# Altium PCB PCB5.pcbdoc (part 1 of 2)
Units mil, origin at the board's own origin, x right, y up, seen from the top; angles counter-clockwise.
Board outline 1951.69 x 1930.99 mil, 2 copper layers (Top Layer, Bottom Layer); 57 components, 38 nets, 209 pads, 95 vias.
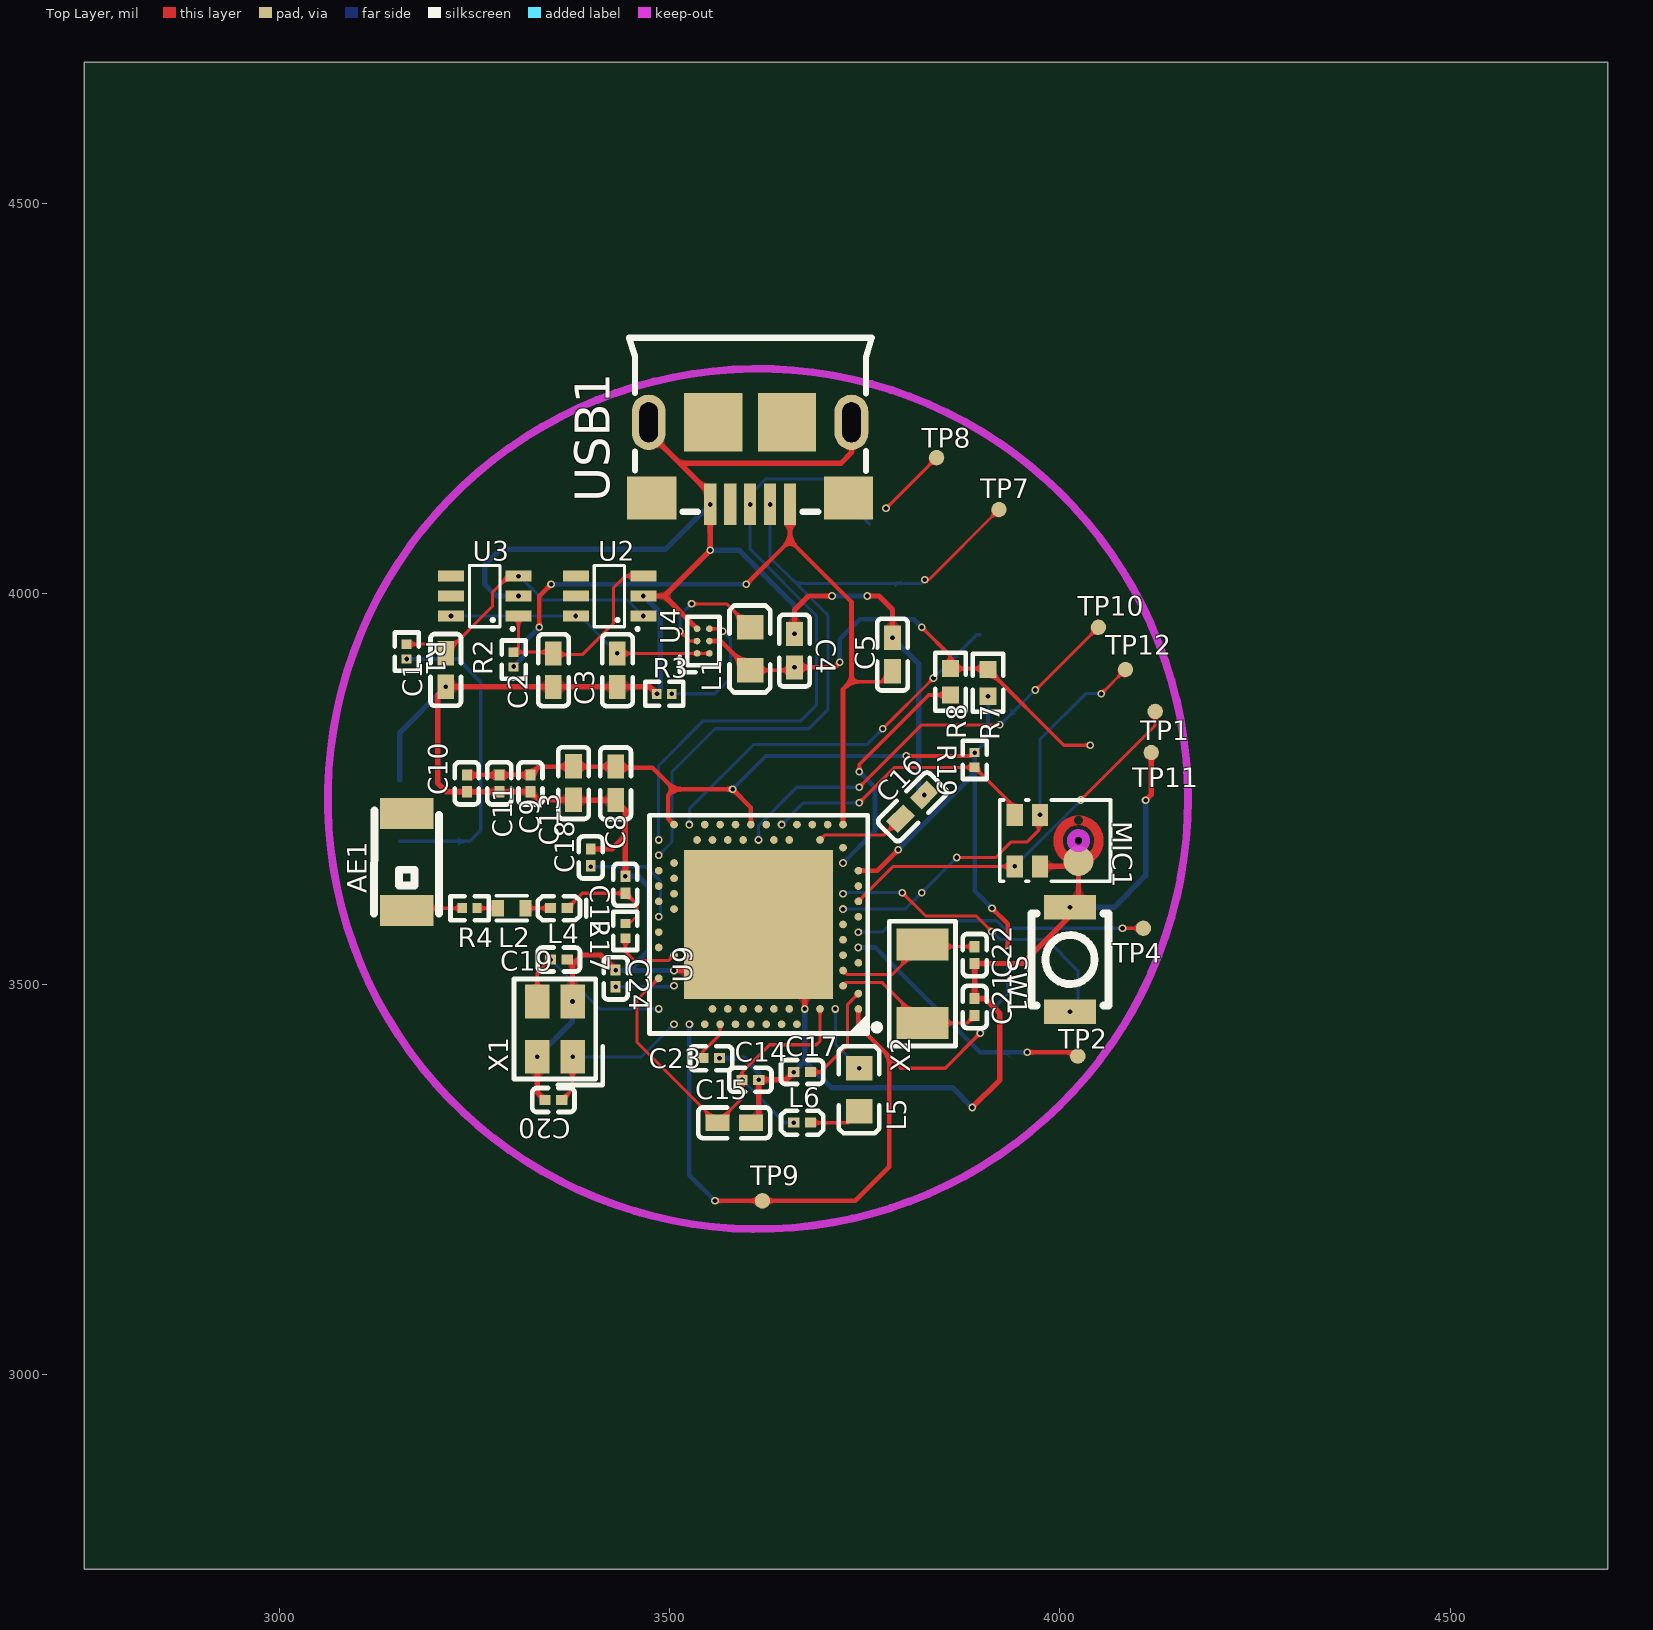
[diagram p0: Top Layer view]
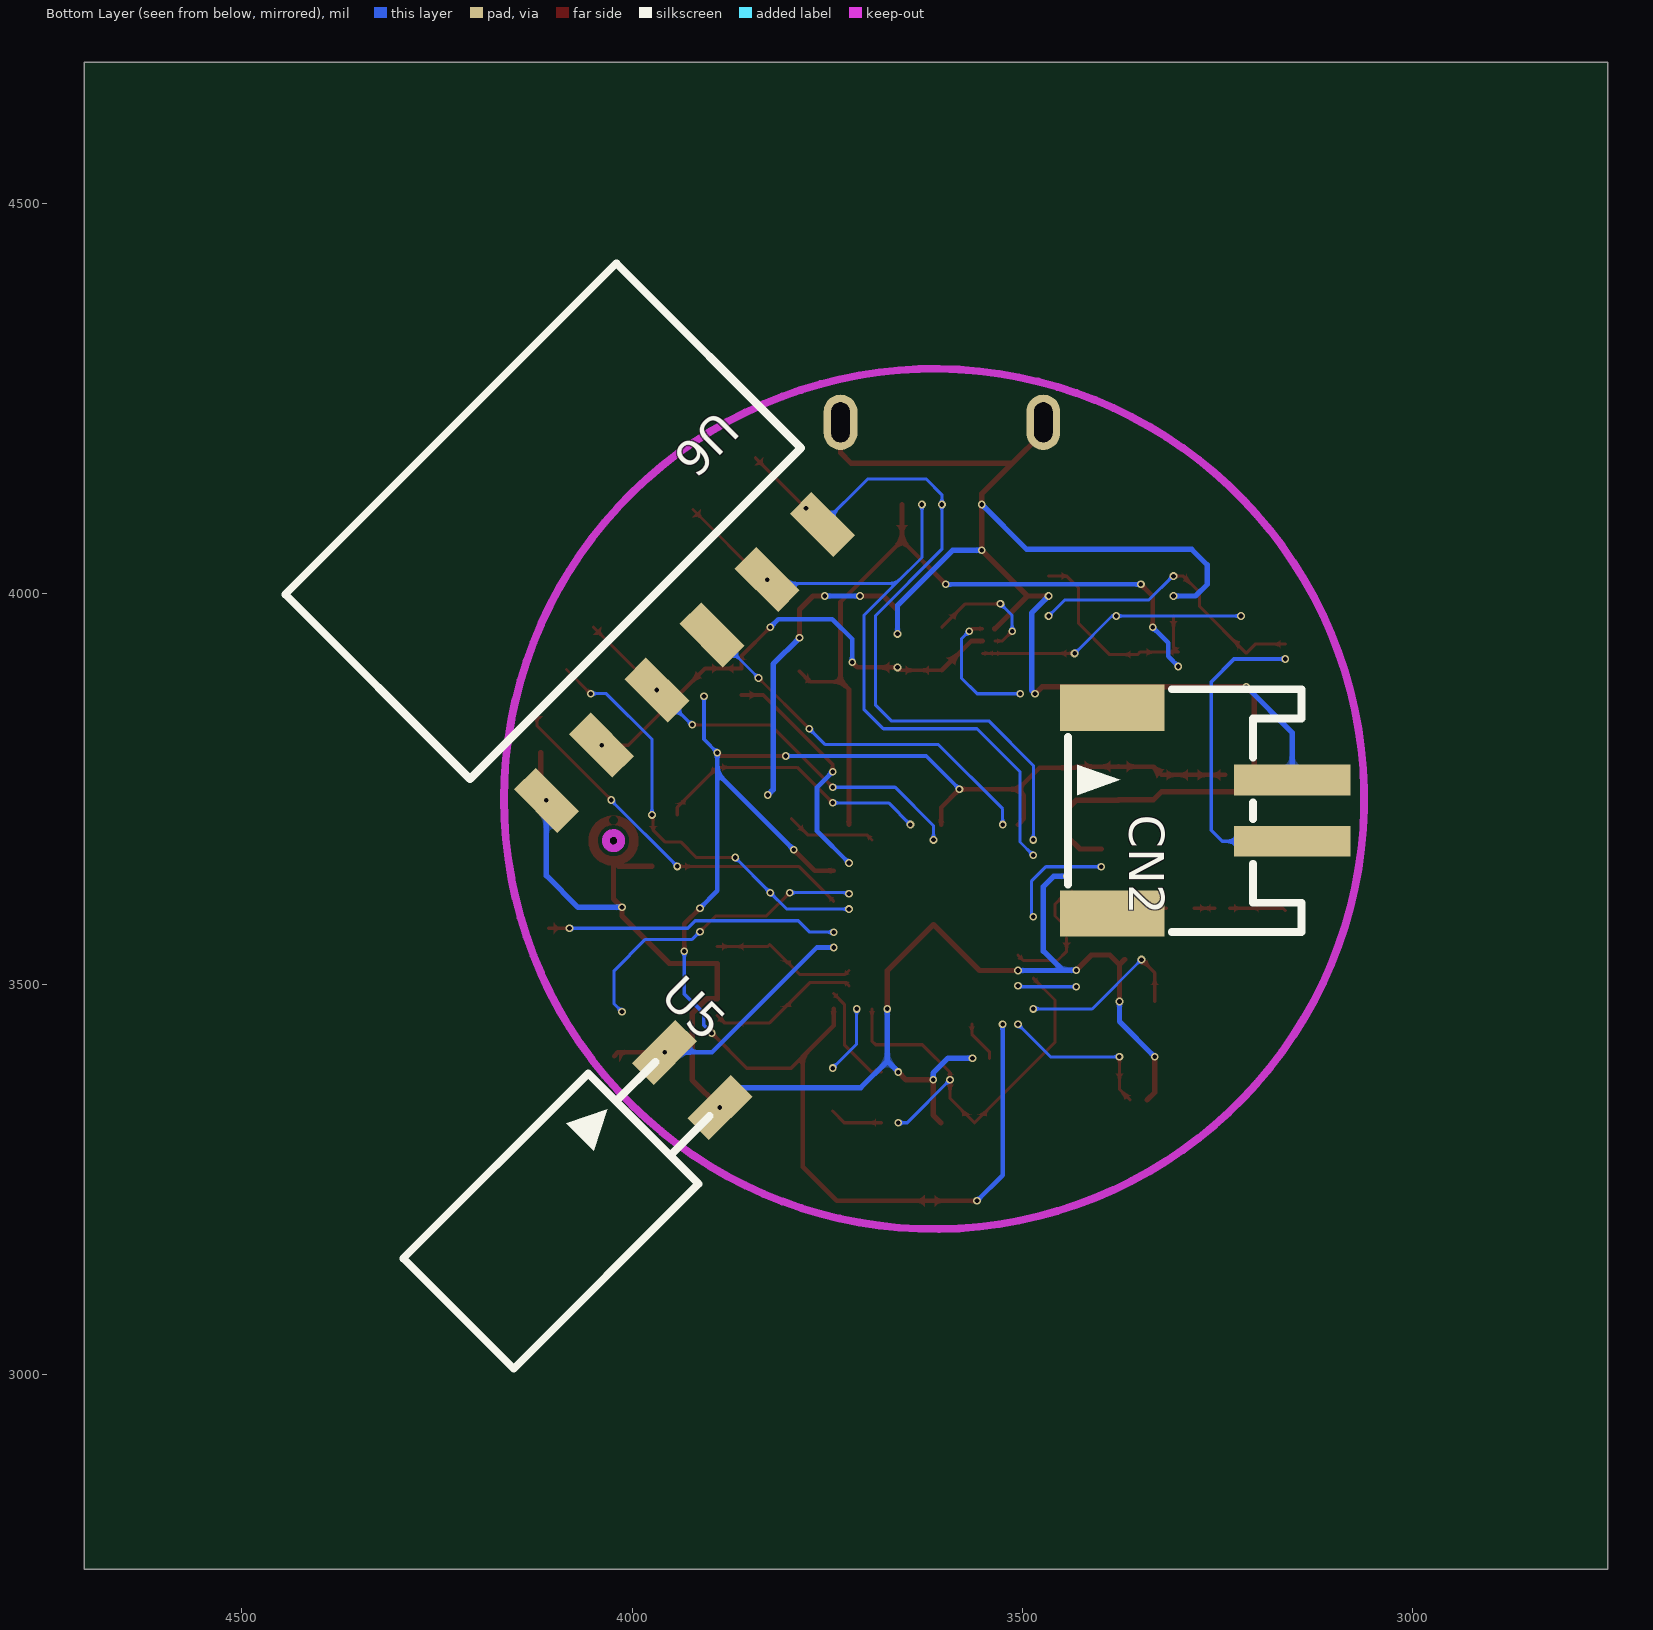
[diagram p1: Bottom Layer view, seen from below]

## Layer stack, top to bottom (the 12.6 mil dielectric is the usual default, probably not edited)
Top Layer: signal copper (thickness not stored)
Dielectric: dielectric 12.6, FR-4, Dk 4.8
Bottom Layer: signal copper (thickness not stored)

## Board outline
4701.69,2750 2750,2750 2750,4680.99 4701.69,4680.99

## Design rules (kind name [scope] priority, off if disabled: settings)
Clearance copperThickness1oz [All] p1: gap=7 ignorepadtopadclearanceinfootprint=FALSE except(4: Track-Track Track-Via Via-Via; 5: SMDPad-Via THPad-Via Via-Hole; 6: Track-SMDPad SMDPad-SMDPad Track-THPad SMDPad-THPad THPad-THPad Track-Fill SMDPad-Fill THPad-Fill Via-Fill Fill-Fill SMDPad-Region THPad-Region Via-Region Fill-Region Region-Region Track-Poly SMDPad-Poly THPad-Poly Via-Poly Fill-Poly Poly-Poly Track-Text SMDPad-Text THPad-Text Via-Text Fill-Text Region-Text Poly-Text Text-Text Track-Hole SMDPad-Hole THPad-Hole Fill-Hole Region-Hole Poly-Hole Text-Hole; 11.8: Track-Region Region-Poly Track-Sheet SMDPad-Sheet THPad-Sheet Via-Sheet Fill-Sheet Region-Sheet Poly-Sheet Text-Sheet Sheet-Hole)
Clearance copperThickness2oz [All] p1: gap=7 ignorepadtopadclearanceinfootprint=FALSE except(6: Track-SMDPad SMDPad-SMDPad Track-THPad SMDPad-THPad THPad-THPad Track-Via SMDPad-Via THPad-Via Via-Via Track-Fill SMDPad-Fill THPad-Fill Via-Fill Fill-Fill SMDPad-Region THPad-Region Via-Region Fill-Region Region-Region Track-Poly SMDPad-Poly THPad-Poly Via-Poly Fill-Poly Poly-Poly Track-Text SMDPad-Text THPad-Text Via-Text Fill-Text Region-Text Poly-Text Text-Text Track-Hole SMDPad-Hole THPad-Hole Via-Hole Fill-Hole Region-Hole Poly-Hole Text-Hole; 8: Track-Track; 11.8: Track-Region Region-Poly Track-Sheet SMDPad-Sheet THPad-Sheet Via-Sheet Fill-Sheet Region-Sheet Poly-Sheet Text-Sheet Sheet-Hole)
DiffPairsRouting differentialPair [All] p1: maxuncoupledlength=10 maxlimit=6 mostfreqgap=6 toplayer_minwidth=5 toplayer_prefwidth=10 toplayer_maxwidth=100 bottomlayer_minwidth=5 bottomlayer_prefwidth=10 bottomlayer_maxwidth=100
PasteMaskExpansion pasteMaskExpansion [All] p1:
PlaneConnect innerPlane [All] p1: planeconnectstyle=Relief reliefexpansion=20 reliefentries=4 reliefconductorwidth=10 reliefairgap=10
PolygonConnect copperRegion [All] p1: connectstyle=Relief reliefentries=4 reliefconductorwidth=10 polygonreliefangle="90 Angle" airgapwidth=10
RoutingVias viaSize [All] p1: viastyle="Through Hole" holewidth=5.9 minholewidth=5.9 maxholewidth=5.9 width=9.8 minwidth=9.8 maxwidth=9.8
SolderMaskExpansion solderMaskExpansion [All] p1: useseparateexpansions=TRUE expansion=2 expansionbottom=2
Width copperLine [All] p1: maxlimit=4 minlimit=4 preferedwidth=4
Width Source [All] p1: maxlimit=6 minlimit=5 preferedwidth=5
Width Ground [All] p1: maxlimit=7 minlimit=7 preferedwidth=7

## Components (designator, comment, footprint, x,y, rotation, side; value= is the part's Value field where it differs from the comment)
AE1 "2450AT18A100E" ANT-SMD_L3.2-W1.6 3162.94,3656.5 r90 top
C1 "CL05A105KQ5NNNC" C0402 3212.94,3902.61 r90 top
C2 "CL05A105KQ5NNNC" C0402 3350.93,3902.24 r90 top
C3 "CL05A106MP5NUNC" C0402 3432.94,3902.24 r90 top
C4 "GRM155R60J226ME11D" C0402 3659.84,3927.24 r270 top
C5 "C1005X6S0G475M050BC" C0402 3785.42,3922.24 r90 top
C8 "CL05A105KQ5NNNC" C0402 3430.67,3757.24 r90 top
C9 "GRM033C71C104KE14D" C0201 3321.52,3757.24 r270 top
C10 "GRM033C71C104KE14D" C0201 3239.95,3757.24 r270 top
C11 "GRM033C71C104KE14D" C0201 3281.61,3757.24 r270 top
C12 "0201CG0R5B250NT" C0201 3443.14,3627.24 r270 top
C13 "CL05A475KP5NRNC" C0402 3376.68,3757.65 r90 top
C14 "CL03A473KQ3NNNC" C0201 3603.34,3377.24 r0 top
C15 "GRM155R70J105KA12D" C0402 3582.58,3322.24 r180 top
C16 "CL05A475KP5NRNC" C0402 3810.9,3727.1 r225 top
C17 "CL03A104KQ3NNNC" C0201 3669.53,3387.24 r180 top
C18 "GRM0335C1E821JA01D" C0201 3398.74,3662.24 r270 top
C19 "GRM0335C1E120GA01D" C0201 3358.01,3531.44 r180 top
C20 "GRM0335C1E120GA01D" C0201 3350.91,3351.44 r0 top
C21 "GRM0335C1E120GA01D" C0201 3890.77,3470.64 r270 top
C22 "GRM0335C1E120GA01D" C0201 3890.77,3537.24 r90 top
C23 "GRM0335C1E821JA01D" C0201 3552.94,3405.02 r180 top
C24 "GRM0335C1E821JA01D" C0201 3430.67,3507.24 r270 top
CN2 "S2B-PH-SM4-TB(LF)(SN)" CONN-SMD_P2.00_S2B-PH-SM4-TB-LF-SN 3269.28,3722.24 r270 bottom
L1 "SLM16082R2MIT" L0603 3602.94,3929.69 r90 top
L2 "LQW15AN3N9C00D" IND-SMD_L1.0-W0.5-2 3297.4,3597.24 r180 top
L4 "LQP03TG2N7B02D" L0201-RD 3358.01,3597.24 r180 top
L5 "MLZ1608N100LT000" L0603 3742.99,3364.86 r90 top
L6 "LQP03TN15NJ02D" L0201 3669.53,3322.4 r0 top
MIC1 "MSM261D3526Z1CM" OCLGA-6_L3.5-W2.7-TL-MSM261D3526Z1CM 3982.94,3683.78 r90 top
R1 "RC0201JR-070RL" R0201 3162.94,3926.06 r90 top
R2 "RC0201JR-070RL" R0201 3299.92,3915.82 r90 top
R3 "RC0201FR-0756K2L" R0201 3492.94,3871.97 r0 top
R4 "RC0201JR-070RL" R0201 3243.55,3597.24 r180 top
R7 "RC0402FR-070RL" R0402 3907.78,3886.06 r270 top
R8 "RC0402FR-070RL" R0402 3859.77,3887.43 r270 top
R17 "RC0201JR-070RL" R0201 3443.14,3568.22 r270 top
R19 "RC0201JR-070RL" R0201 3890.77,3787.24 r90 top
SW1 "B3U-1000P" KEY-SMD_B3U-1000PM 4012.94,3531.44 r90 top
TP1 "Test-Point" Test-Point-0.5mm 4121.98,3849.41 r0 top
TP2 "Test-Point" Test-Point-0.5mm 4022.94,3407.75 r0 top
TP4 "Test-Point" Test-Point-0.5mm 4106.98,3571.52 r0 top
TP7 "Test-Point" Test-Point-0.5mm 3921.98,4108.16 r0 top
TP8 "Test-Point" Test-Point-0.5mm 3841.98,4174.64 r0 top
TP9 "Test-Point" Test-Point-0.5mm 3618.7,3222.24 r0 top
TP10 "Test-Point" Test-Point-0.5mm 4049.35,3957.24 r0 top
TP11 "Test-Point" Test-Point-0.5mm 4116.98,3796.75 r0 top
TP12 "Test-Point" Test-Point-0.5mm 4084.03,3903.1 r0 top
U2 "LM66100DCKT_C2832141" SC-70-6_L2.0-W1.3-P0.65-LS2.1-BL 3422.94,3997.24 r90 top
U3 "LM66100DCKT_C2832141" SC-70-6_L2.0-W1.3-P0.65-LS2.1-BL 3262.94,3997.24 r90 top
U4 "MAX38640AENT+" WLP-6_L1.4-W0.9-R2-C3-P0.40-TL 3542.94,3939.58 r90 top
U5 "X6511FRS-02-C85D30" HDR-SMD_2P-P2.54-H-F-L11.5 3922.94,3377.24 r225 bottom
U6 "X6511FRS-06-C85D30" HDR-SMD_6P-P2.54-H-F-L11.5 3932.94,3912.24 r315 bottom
U9 "NRF52840-QIAA-R" AQFN-73_L7.0-W7.0-P0.50-BL-EP4.8 3613.77,3576.44 r90 top
USB1 "10118193-0001LF" MICRO-USB-SMD_10118193-0001LF 3602.94,4167.24 r180 top
X1 "Q22FA1280002500" CRYSTAL-SMD_4P-L2.0-W1.6-BL 3352.82,3442.24 r90 top
X2 "NX3215SA-32.768K-STD-MUA-9" CRYSTAL-SMD_L3.2-W1.5-1 3823.74,3500.46 r90 top

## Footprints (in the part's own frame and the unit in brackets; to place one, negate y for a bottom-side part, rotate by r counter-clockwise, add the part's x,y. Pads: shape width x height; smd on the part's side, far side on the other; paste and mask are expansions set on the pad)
ANT-SMD_L3.2-W1.6 [mm]
  rect 1x1.75 smd: 1(-1.578,0) 2(1.578,0)
  silkscreen extent -1.68,-1.05 1.68,1.06
AQFN-73_L7.0-W7.0-P0.50-BL-EP4.8 [mm]
  rect 4.85x4.85 smd: 0(0,0)
  round 0.25 smd: A8(-3.25,-1.25) A10(-3.25,-0.75) A12(-3.25,-0.25) A14(-3.25,0.25) A16(-3.25,0.75) A18(-3.25,1.25) A20(-3.25,1.75) A22(-3.25,2.25) A23(-3.25,2.75) AA24(2.25,3.25) AB2(2.5,-2.75) AC5(2.75,-2) AC9(2.75,-1) AC11(2.75,-0.5) AC13(2.75,0) AC15(2.75,0.5) AC17(2.75,1) AC19(2.75,1.5) AC21(2.75,2) AC24(2.75,3.25) AD2(3.25,-2.75) AD4(3.25,-2.25) AD6(3.25,-1.75) AD8(3.25,-1.25) AD10(3.25,-0.75) AD12(3.25,-0.25) AD14(3.25,0.25) AD16(3.25,0.75) AD18(3.25,1.25) AD20(3.25,1.75) AD22(3.25,2.25) AD23(3.25,2.75) B1(-2.75,-3.25) B3(-2.75,-2.5) B5(-2.75,-2) B7(-2.75,-1.5) B9(-2.75,-1) B11(-2.75,-0.5) B13(-2.75,0) B15(-2.75,0.5) B17(-2.75,1) B19(-2.75,1.5) B24(-2.75,3.25) C1(-2.25,-3.25) D2(-2,-2.75) D23(-2,2.75) E24(-1.75,3.25) F2(-1.5,-2.75) F23(-1.5,2.75) G1(-1.25,-3.25) H2(-1,-2.75) H23(-1,2.75) J1(-0.75,-3.25) J24(-0.75,3.25) K2(-0.5,-2.75) L1(-0.25,-3.25) L24(-0.25,3.25) M2(0,-2.75) N1(0.25,-3.25) N24(0.25,3.25) P2(0.5,-2.75) P23(0.5,2.75) R1(0.75,-3.25) R24(0.75,3.25) T2(1,-2.75) T23(1,2.75) U1(1.25,-3.25) U24(1.25,3.25) V23(1.5,2.75) W1(1.75,-3.25) W24(1.75,3.25) Y2(2,-2.75) Y23(2,2.75)
  silkscreen extent -3.55,-3.95 3.55,3.55
C0201 [mil]
  rect 14.51x12.76 smd: 1(-10.8,0) 2(10.8,0)
  silkscreen extent -27,-15 27,15
C0402 [mm]
  rect 0.79x0.54 smd: 1(-0.545,0) 2(0.545,0)
  silkscreen extent -1.17,-0.5 1.17,0.5
CONN-SMD_P2.00_S2B-PH-SM4-TB-LF-SN [mm]
  rect 1x3.8 smd: 1(-1,2.925) 2(1,2.925)
  rect 1.5x3.4 smd: 3(3.35,-2.925) 4(-3.35,-2.925)
  silkscreen extent -3.95,-4.37 3.95,3.22
CRYSTAL-SMD_4P-L2.0-W1.6-BL [mm]
  rect 1.1x0.8 smd: 1(-0.9,-0.575) 2(0.9,-0.575) 3(0.9,0.575) 4(-0.9,0.575)
  silkscreen extent -1.82,-1.56 1.64,1.33
CRYSTAL-SMD_L3.2-W1.5-1 [mm]
  rect 1.05x1.7 smd: 1(-1.275,0) 2(1.275,0)
  silkscreen extent -2.03,-1.08 2.03,1.08
HDR-SMD_2P-P2.54-H-F-L11.5 [mm]
  rect 1x2 smd: 1(-1.27,0) 2(1.27,0)
  silkscreen extent -2.54,-10.76 2.54,-0.43
HDR-SMD_6P-P2.54-H-F-L11.5 [mm]
  rect 1x2 smd: 1(-6.35,0) 2(-3.81,0) 3(-1.27,0) 4(1.27,0) 5(3.81,0) 6(6.35,0)
  silkscreen extent -7.62,-10.75 7.62,-2.25
IND-SMD_L1.0-W0.5-2 [mm]
  rect 0.4x0.55 smd: 1(-0.45,0) 2(0.45,0)
  silkscreen extent -0.5,-0.41 0.5,0.41
KEY-SMD_B3U-1000PM [mm]
  rect 0.8x1.7 smd: 1(-1.7,0) 2(1.7,0)
  silkscreen extent -1.5,-1.25 1.5,1.25
L0201 [mil]
  rect 14.51x12.76 smd: 1(-10.8,0) 2(10.8,0)
  silkscreen extent -27,-15 27,15
L0201-RD [mil]
  rect 14.51x12.76 smd: 1(-10.8,0) 2(10.8,0)
  silkscreen extent -35,-15 27,15
L0603 [mm]
  rect 0.8x0.864 smd: 1(-0.7,0) 2(0.7,0)
  silkscreen extent -1.42,-0.65 1.41,0.67
MICRO-USB-SMD_10118193-0001LF [mm]
  rect 0.4x1.35 smd: 1(-1.3,1.338) 2(-0.65,1.338) 3(0,1.338) 4(0.65,1.338) 5(1.3,1.338)
  oval 1.1x1.8 hole 0.6 slot 1.3 at 90 deg copper offset 0.001,-0.001: 6(-3.301,-1.337)
  oval 1.1x1.8 hole 0.6 slot 1.3 at 90 deg copper offset -0.001,-0.001: 6(3.301,-1.337)
  rect 1.6x1.4 smd: 7(-3.2,1.119) 8(3.2,1.119)
  rect 1.9x1.9 smd: 7(-1.2,-1.337) 8(1.2,-1.337)
  silkscreen extent -3.96,-4.09 3.94,1.57
OCLGA-6_L3.5-W2.7-TL-MSM261D3526Z1CM [mm]
  rect 0.725x0.522 smd: 1(-0.838,1.038) 2(-0.838,0.216) 4(0.838,0.216) 5(0.838,1.038)
  round 0.975 smd: 3(-0.663,-1.038)
  Top Layer region: 279 vertices and 0 holes, not listed, extent -0.813,-1.85 0.813,-0.224
  Multi-Layer board cut-out: 0,-1.287 0.109,-1.263 0.196,-1.193 0.244,-1.093 0.244,-0.982 0.196,-0.881 0.109,-0.812 0,-0.787 0,-0.787 -0.108,-0.812 -0.195,-0.881 -0.244,-0.982 -0.244,-1.093 -0.195,-1.193 -0.108,-1.263 0,-1.287
  Multi-Layer keep-out circle w0.254: c0,-1.037 r0.25
  silkscreen extent -1.32,-2.08 1.33,1.52
R0201 [mil]
  rect 11.93x12.76 smd: 1(-9.51,0) 2(9.51,0)
  silkscreen extent -24,-15 24,15
R0402 [mm]
  rect 0.566x0.54 smd: 1(-0.433,0) 2(0.433,0)
  silkscreen extent -0.94,-0.5 0.94,0.5
SC-70-6_L2.0-W1.3-P0.65-LS2.1-BL [mm]
  rect 0.35x0.85 smd: 1(-0.65,-1.1) 2(0,-1.1) 3(0.65,-1.1) 4(0.65,1.1) 5(0,1.1) 6(-0.65,1.1)
  silkscreen extent -1.12,-0.96 1,0.5
Test-Point-0.5mm [mm]
  round 0.5 smd: 1(0,0)
WLP-6_L1.4-W0.9-R2-C3-P0.40-TL [mil]
  round 8.5 smd: A1(-15.75,7.87) A2(0,7.87) A3(15.75,7.87) B1(-15.75,-7.87) B2(0,-7.87) B3(15.75,-7.87)
  silkscreen extent -40,-21 31,30

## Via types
v1: diameter 9.84, hole 5.91, Top Layer to Bottom Layer, 95 vias

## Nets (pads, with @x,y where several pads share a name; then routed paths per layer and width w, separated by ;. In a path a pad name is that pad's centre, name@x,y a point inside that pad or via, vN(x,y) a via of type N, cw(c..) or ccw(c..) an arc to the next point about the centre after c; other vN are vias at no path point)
$1N2608: C2.2 R2.2 U2.3 U3.1 | length 284.9
  Top Layer w4: U3.1@3306.25,3971.65 3306.25,3931.67 R2.2@3299.92,3925.33 3349.3,3925.33 C2.2@3350.93,3923.7 3352.39,3922.24 3387.94,3922.24 3427.94,3962.24 3427.94,4007.83 3442.94,4022.83 U2.3@3466.25,4022.83
$1N2669: 
$1N2785: R3.2 U4.B3 | length 166.4
  Top Layer w4: U4.B3@3550.81,3955.33 3564.85,3955.33 v1(3567.94,3952.24)
  Bottom Layer w4: v1(3502.45,3871.97) 3557.67,3871.97 3577.94,3892.24 3577.94,3942.24 v1(3567.94,3952.24)
$1N3382: AE1.1 R4.2 | length 72.3
  Top Layer w4: AE1.1@3162.94,3594.37 3165.82,3597.24 R4.2@3234.04,3597.24
$1N5000: L2.2 R4.1 | length 26.6
  Top Layer w4: R4.1@3253.06,3597.24 L2.2@3279.68,3597.24
$1N15802: C1.2 R1.2 U2.1 U3.3 | length 380.8
  Top Layer w4: R1.2@3162.94,3935.57 3201.44,3935.57 C1.2@3212.94,3924.07 3272.94,3984.07 3272.94,4002.24 3293.53,4022.83 v1(3306.25,4022.83)
  Bottom Layer w4: v1(3306.25,4022.83) 3307.35,4022.83 3337.94,3992.24 3445.66,3992.24 v1(3466.25,3971.65)
$1N38769: C16.2 U9.AC5 | length 114.5
  Top Layer w4: U9.AC5@3692.51,3684.71 3699.04,3691.24 3775.04,3691.24 C16.2@3795.73,3711.93
$1N38954: C18.2 U9.N24 | length 143.6
  Bottom Layer w4: v1(3398.74,3650.43) 3469.75,3650.43 3487.94,3632.24 3487.94,3588.42 v1(3485.81,3586.29)
$1N39111: C12.2 L4.1 R17.1 | length 136.7
  Top Layer w4: L4.1@3368.81,3597.24 3388.01,3616.44 C12.2@3443.14,3616.44 3443.74,3616.44 3457.94,3602.24 3457.94,3587.24 3448.43,3577.73 R17.1@3443.14,3577.73
$1N39307: L5.1 L6.2 | length 68.8
  Top Layer w4: L6.2@3680.33,3322.4 3728.09,3322.4 L5.1@3742.99,3337.3
$1N39479: C23.2 U9.A18 | length 52.8
  Top Layer w4: C23.2@3542.14,3405.02 3542.14,3413.4 3564.56,3435.82 U9.A18@3564.56,3448.49
$1N39540: C24.2 U9.D23 | length 75.3
  Bottom Layer w4: v1(3430.67,3496.63) 3504.43,3496.63 v1(3505.5,3497.7)
+3V3: C4.2 L1.1 R7.1 R8.1 U4.B2 U6.5 | length 624.6
  Top Layer w4.68: L1.1@3602.94,3902.13 3656.19,3902.13 v1(3659.84,3905.78) ; v1(3822.94,3957.24) 3859.77,3920.42 R8.1@3859.77,3904.47 3906.41,3904.47 R7.1@3907.78,3903.1 4004.7,3806.18 v1(4039.01,3806.18)
  Top Layer w5.91: U4.B2@3550.81,3939.58 3565.49,3939.58 L1.1@3602.94,3902.13 ; v1(3659.84,3905.78) 3711.48,3905.78 v1(3717.94,3912.24)
  Bottom Layer w5.91: v1(3717.94,3912.24) 3717.94,3942.24 3743.31,3967.61 3812.58,3967.61 v1(3822.94,3957.24)
+BATT: CN2.2 R1.1 | length 406.9
  Bottom Layer w4.68: CN2.2@3154.12,3682.87 3243.57,3682.87 3257.94,3697.24 3257.94,3887.24 3228.64,3916.55 v1(3162.94,3916.55)
AGND: C1.1 C2.1 C3.1 C4.1 C5.2 C8.1 C9.2 C10.2 C11.2 C12.1 C13.1 C14.2 C15.1 C16.1 C17.2 C18.1 C19.1 C20.1 C21.1 C22.1 C23.1 C24.1 CN2.1 MIC1.2 MIC1.3 R3.1 SW1.2 TP11.1 U2.2 U3.2 U4.A3 U5.2 U6.6 U9.0 U9.B7 U9.F23 USB1.5 USB1.6 X1.2 X1.4 | length 4752.8
  Top Layer w6.89: v1(3330.19,3406.81) 3330.19,3361.37 C20.1@3340.11,3351.44 ; C19.1@3368.81,3531.44 3375.45,3524.8 ; v1(3375.45,3477.67) 3375.45,3524.8 ; C18.1@3398.74,3673.04 3426.17,3673.04 3443.14,3690.02 ; C24.1@3430.67,3518.04 3411.47,3537.24 3387.89,3537.24 3375.45,3524.8 ; v1(3443.14,3638.04) 3443.14,3690.02 ; v1(3466.25,3997.24) 3493.16,3997.24 ; USB1.6@3472.98,4219.89 3473.02,4207.16 3512.94,4167.24 ; R3.1@3483.43,3871.97 3474.62,3880.78 C3.1@3432.94,3880.78 C2.1@3350.93,3880.78 3350.56,3881.15 v1(3212.94,3881.15) 3202.94,3871.15 3202.94,3757.24 3213.74,3746.44 C10.2@3239.95,3746.44 C11.2@3281.61,3746.44 C9.2@3321.52,3746.44 3331.78,3736.19 C13.1@3376.68,3736.19 3377.09,3735.78 C8.1@3430.67,3735.78 3443.14,3723.31 3443.14,3690.02 ; v1(3505.5,3517.39) 3554.72,3517.39 U9.0@3613.77,3576.44 3672.82,3517.39 v1(3672.82,3468.17) ; U4.A3@3535.07,3955.33 3493.16,3997.24 ; C15.1@3604.04,3322.24 3614.14,3332.35 v1(3614.14,3377.24) 3648.73,3377.24 v1(3658.73,3387.24) ; v1(3659.84,3948.7) 3659.84,3979.14 3677.94,3997.24 v1(3707.94,3997.24) ; USB1.6@3732.9,4219.87 3732.86,4181.02 3719.09,4167.24 3512.94,4167.24 ; v1(3752.94,3997.24) 3767.94,3997.24 3785.42,3979.77 v1(3785.42,3943.7) ; v1(3887.59,3341.89) 3922.94,3377.24 3922.94,3462.24 3903.74,3481.44 C21.1@3890.77,3481.44 C22.1@3890.77,3526.44 3952.14,3526.44 4012.94,3587.24 v1(4012.94,3598.37) 4023.79,3609.22 MIC1.3@4023.79,3657.69 4016.89,3650.79 MIC1.2@3974.45,3650.79 ; v1(4109.72,3735.47) 4116.98,3742.72 TP11.1@4116.98,3796.75 ; 3493.16,3997.24 v1(3551.76,4055.84) v1(3551.76,4114.58) 3551.76,4128.42 3512.94,4167.24
  Bottom Layer w6.89: CN2.1@3154.12,3761.61 3154.12,3822.32 v1(3212.94,3881.15) ; v1(3306.25,3997.24) 3277.94,3997.24 3262.94,4012.24 3262.94,4037.24 3282.94,4057.24 3494.43,4057.24 v1(3551.76,4114.58) ; v1(3330.19,3406.81) 3375.45,3452.07 v1(3375.45,3477.67) ; v1(3443.14,3638.04) 3459.98,3638.04 3472.94,3625.08 3472.94,3542.24 3448.56,3517.86 v1(3430.67,3517.86) 3431.13,3517.39 v1(3505.5,3517.39) ; v1(3466.25,3997.24) 3487.94,3975.55 3487.94,3876.31 v1(3483.61,3871.97) ; v1(3551.76,4055.84) 3589.34,4055.84 3659.84,3985.35 v1(3659.84,3948.7) ; v1(3563.74,3405.02) 3595.17,3405.02 3614.14,3386.05 v1(3614.14,3377.24) ; v1(3658.73,3387.24) 3672.82,3401.34 ; v1(3672.82,3468.17) 3672.82,3401.34 ; v1(3707.94,3997.24) v1(3752.94,3997.24) ; v1(3785.42,3943.7) 3819.19,3909.93 3819.19,3749.17 v1(3826.08,3742.28) ; v1(3887.59,3341.89) 3862.23,3367.24 3706.92,3367.24 3672.82,3401.34 ; v1(4012.94,3598.37) 4069.07,3598.37 4109.72,3639.02 v1(4109.72,3735.47)
ANT: L2.1 L4.2 | length 32.1
  Top Layer w4: L2.1@3315.11,3597.24 L4.2@3347.21,3597.24
BUTTON: SW1.1 U9.T2 | length 399.8
  Top Layer w4: v1(3797.94,3617.24) 3827.94,3587.24 3892.94,3587.24 v1(3912.94,3567.24)
  Bottom Layer w4: v1(3722.04,3615.81) 3723.47,3617.24 v1(3797.94,3617.24) ; v1(3912.94,3567.24) 3922.94,3557.24 3982.94,3557.24 4022.94,3517.24 4022.94,3474.52 v1(4012.94,3464.52)
DCC: L5.2 U9.B3 | length 88.5
  Bottom Layer w4: v1(3712.19,3468.17) 3712.19,3423.21 v1(3742.99,3392.41)
DEC1: C17.1 U9.C1 | length 133.4
  Top Layer w4: C17.1@3680.33,3387.24 3692.94,3387.24 3727.94,3422.24 3727.94,3474.08 U9.C1@3741.72,3487.86
DEC46: C14.1 C15.2 L6.1 U9.B5 U9.E24 | length 564
  Top Layer w4: U9.E24@3485.82,3507.54 3457.94,3479.66 3457.94,3425.42 C15.2@3561.12,3322.24 3592.54,3353.67 v1(3592.54,3377.24) 3592.54,3386.84 3627.94,3422.24 3687.94,3422.24 3692.51,3426.82 U9.B5@3692.51,3468.17
  Bottom Layer w4: v1(3592.54,3377.24) 3647.38,3322.4 v1(3658.73,3322.4)
GPIO2: TP4.1 U9.L1 | length 375.3
  Top Layer w4: v1(4080.14,3571.52) TP4.1@4106.98,3571.52
  Bottom Layer w4: v1(3741.72,3566.6) 3772.3,3566.6 3786.94,3581.24 3918.94,3581.24 3928.67,3571.52 v1(4080.14,3571.52)
LX: L1.2 U4.A2 | length 156
  Top Layer w4: v1(3512.94,3952.24) 3525.6,3939.58 U4.A2@3535.07,3939.58 ; v1(3527.94,3987.24) 3572.94,3987.24 L1.2@3602.94,3957.24
  Bottom Layer w4: v1(3512.94,3952.24) 3512.94,3972.24 v1(3527.94,3987.24)
MIC_EN: MIC1.5 R19.1 U9.AD10 | length 360.1
  Top Layer w4: v1(3742.94,3732.24) 3788.43,3777.73 R19.1@3890.77,3777.73 3942.09,3726.41 MIC1.5@3942.09,3716.78
  Bottom Layer w4: v1(3643.31,3704.4) 3671.15,3732.24 v1(3742.94,3732.24)
NRF_ANT: R17.2 U9.H23 | length 86.9
  Top Layer w4: R17.2@3443.14,3558.71 3443.14,3541.87 3454.87,3530.15 3498.58,3530.15 U9.H23@3505.5,3537.07
PDM_CLK: MIC1.4 TP12.1 U9.P2 | length 556.5
  Top Layer w4: v1(3867.94,3662.24) 3917.68,3662.24 3937.68,3682.24 3957.94,3682.24 3972.94,3697.24 3972.94,3715.27 v1(3974.45,3716.78) ; v1(4052.94,3872.24) 4053.18,3872.24 TP12.1@4084.03,3903.1
  Bottom Layer w4: v1(3722.04,3596.13) 3801.83,3596.13 v1(3822.94,3617.24) v1(3867.94,3662.24) ; v1(3974.45,3716.78) 3974.45,3813.75 4032.94,3872.24 v1(4052.94,3872.24)
PDM_DATA: MIC1.1 TP1.1 U9.R1 | length 492.1
  Top Layer w4: U9.R1@3741.72,3605.97 3786.55,3650.8 v1(3942.09,3650.8) ; v1(4026.47,3735.95) 4121.98,3831.45 TP1.1@4121.98,3849.41
  Bottom Layer w4: v1(3942.09,3650.8) 4026.47,3735.18 v1(4026.47,3735.95)
PIEZO_READ: TP2.1 U5.1 U9.J1 | length 338.9
  Top Layer w5.91: v1(3958.3,3412.6) 4018.1,3412.6 TP2.1@4022.94,3407.75
  Bottom Layer w5.91: v1(3741.72,3546.93) 3763.26,3546.93 3897.59,3412.6 v1(3958.3,3412.6)
RESET: TP10.1 U6.4 U9.AC13 | length 559.2
  Top Layer w4: v1(3742.94,3752.24) 3822.94,3832.24 v1(3922.94,3832.24) ; v1(3968.3,3876.89) 3968.99,3876.89 TP10.1@4049.35,3957.24
  Bottom Layer w4: v1(3613.77,3684.71) 3613.77,3703.08 3662.94,3752.24 v1(3742.94,3752.24) ; v1(3922.94,3832.24) 3923.65,3832.24 v1(3968.3,3876.89)
SWDCLK: TP7.1 U6.2 U9.AA24 USB1.2 | length 940.1
  Top Layer w4: v1(3826.88,4018.31) 3832.13,4018.31 TP7.1@3921.98,4108.16
  Bottom Layer w4: v1(3485.82,3665.02) 3502.94,3682.14 3502.94,3772.24 3557.94,3827.24 3677.94,3827.24 3702.94,3852.24 3702.94,3972.24 3661.72,4013.47 ; v1(3628.53,4114.57) 3628.53,4046.65 3661.72,4013.47 ; v1(3826.88,4018.31) 3822.04,4013.47 3661.72,4013.47
SWDIO: TP8.1 U6.1 U9.AC24 USB1.3 | length 912.1
  Top Layer w4: v1(3777.05,4109.9) 3777.24,4109.9 TP8.1@3841.98,4174.64
  Bottom Layer w4: v1(3485.82,3684.71) 3485.82,3780.13 3542.94,3837.24 3667.94,3837.24 3687.94,3857.24 3687.94,3972.24 3602.94,4057.24 v1(3602.94,4114.57) 3602.94,4127.24 3622.94,4147.24 3697.94,4147.24 U6.1@3756.17,4089.02
SWO: U6.3 U9.AD22 | length 484.9
  Top Layer w4: v1(3772.94,3827.24) v1(3837.94,3892.24)
  Bottom Layer w4: v1(3525.19,3704.41) 3525.19,3724.49 3607.94,3807.24 3752.94,3807.24 v1(3772.94,3827.24) ; v1(3837.94,3892.24) 3893.3,3947.6 U6.3@3897.59,3947.6
VBUS: C5.1 R2.1 U9.AD2 USB1.1 | length 961.4
  Top Layer w4.68: 3731.63,3887.24 3771.88,3887.24 C5.1@3785.42,3900.78
  Top Layer w5.91: v1(3332.94,3957.24) 3332.94,3997.24 v1(3347.94,4012.24) ; v1(3597.94,4012.24) 3654.12,4068.42 ; USB1.1@3654.12,4114.58 3654.12,4068.42 ; U9.AD2@3722.04,3704.39 3722.04,3877.66 3731.63,3887.24 3732.94,3888.56 3732.94,3989.6 3654.12,4068.42
  Bottom Layer w5.91: v1(3299.92,3906.96) 3312.94,3919.99 3312.94,3937.24 v1(3332.94,3957.24) ; v1(3347.94,4012.24) v1(3597.94,4012.24)
VDD_NRF: C8.2 C9.1 C10.1 C11.1 C13.2 R7.2 R19.2 TP9.1 U9.A22 U9.AD14 U9.AD23 U9.B1 U9.W1 | length 2307
  Top Layer w4.68: 3781.39,3407.24 3796.39,3392.24 3852.94,3392.24 v1(3897.94,3437.24) ; v1(3802.94,3792.24) 3886.26,3792.24 R19.2@3890.77,3796.75
  Top Layer w5.91: C10.1@3239.95,3768.04 C11.1@3281.61,3768.04 C9.1@3321.52,3768.04 3332.18,3778.7 C13.2@3377.09,3778.7 ; C13.2@3376.68,3779.11 C13.2@3377.09,3778.7 ; U9.AD23@3505.5,3704.39 3497.94,3711.96 3497.94,3742.12 3505.5,3749.68 ; v1(3557.94,3222.24) TP9.1@3618.7,3222.24 3737.94,3222.24 3781.39,3265.69 3781.39,3407.24 3741.72,3446.91 U9.B1@3741.72,3468.17 ; U9.AD14@3603.93,3704.39 3603.93,3726.25 v1(3580.5,3749.68) 3505.5,3749.68 ; U9.W1@3741.72,3645.34 3766.04,3645.34 v1(3792.94,3672.24) ; v1(3912.94,3597.24) 3932.94,3577.24 v1(3932.94,3542.24) ; C13.2@3377.09,3778.7 C8.2@3430.67,3778.7 3432.13,3777.24 3477.94,3777.24 3505.5,3749.68
  Bottom Layer w4.68: v1(3580.5,3749.68) 3623.07,3792.24 v1(3802.94,3792.24) ; v1(3890.77,3796.58) 3907.78,3813.59 v1(3907.78,3869.02) ; v1(3897.94,3437.24) 3907.94,3447.24 3907.94,3462.24 3932.94,3487.24 v1(3932.94,3542.24)
  Bottom Layer w5.91: v1(3525.2,3448.5) 3525.2,3254.99 v1(3557.94,3222.24) ; v1(3792.94,3672.24) 3890.77,3770.07 ; v1(3890.77,3796.58) 3890.77,3770.07 ; v1(3912.94,3597.24) 3890.77,3619.41 3890.77,3770.07
VDDH: R8.2 U9.Y2 | length 305.1
  Top Layer w4.68: v1(3742.94,3772.24) 3742.94,3781.31 3832.02,3870.39 R8.2@3859.77,3870.39
  Bottom Layer w5.91: v1(3722.04,3655.18) 3762.94,3696.08 3762.94,3752.24 v1(3742.94,3772.24)
XC1: C19.2 U9.B24 X1.3 | length 225.6
  Top Layer w4: X1.3@3330.18,3477.67 3330.18,3514.42 v1(3347.21,3531.44)
  Bottom Layer w4: v1(3347.21,3531.44) 3410.48,3468.17 v1(3485.82,3468.17)
XC2: C20.2 U9.A23 X1.1 | length 208.4
  Top Layer w4: C20.2@3361.71,3351.44 3375.46,3365.19 v1(3375.46,3406.81)
  Bottom Layer w4: v1(3375.46,3406.81) 3463.82,3406.81 v1(3505.51,3448.5)
XL1: C21.2 U9.D2 X2.1 | length 196.1
  Top Layer w4: U9.D2@3722.04,3497.7 3726.58,3502.24 3771.77,3502.24 X2.1@3823.74,3450.27 3881.2,3450.27 C21.2@3890.77,3459.84
XL2: C22.2 U9.F2 X2.2 | length 187.9
  Top Layer w4: U9.F2@3722.04,3517.39 3727.19,3512.24 3785.33,3512.24 X2.2@3823.74,3550.66 3826.36,3548.04 C22.2@3890.77,3548.04
pads on no net: AE1.2 C3.2 CN2.3 CN2.4 U2.4 U2.5 U2.6 U3.4 U3.5 U3.6 U4.A1 U4.B1 U9.A8 U9.A10 U9.A12 U9.A14 U9.A16 U9.A20 U9.AB2 U9.AC9 U9.AC11 U9.AC15 U9.AC17 U9.AC19 U9.AC21 U9.AD4 U9.AD6 U9.AD8 U9.AD12 U9.AD16 U9.AD18 U9.AD20 U9.B9 U9.B11 U9.B13 U9.B15 U9.B17 U9.B19 U9.G1 U9.H2 U9.J24 U9.K2 U9.L24 U9.M2 U9.N1 U9.P23 U9.R24 U9.T23 U9.U1 U9.U24 U9.V23 U9.W24 U9.Y23 USB1.4 USB1.7 USB1.8
copper on no net: | length 351.1
  Top Layer w4: v1(3432.94,3923.7) 3534.94,3923.7 3535.07,3923.83 3550.81,3923.83
  Bottom Layer w4: v1(3219.63,3971.65) v1(3379.63,3971.65) 3384.99,3971.65 v1(3432.94,3923.7)

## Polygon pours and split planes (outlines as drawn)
AGND on Bottom Layer (solid, remove dead copper, pour order 2): 4215.02,3732.24 ccw(c3612.94,3732.24) 3010.86,3732.24 ccw(c3612.94,3732.24)
AGND on Top Layer (solid, remove dead copper, pour order 2): 4225.89,3732.24 ccw(c3612.94,3732.24) 3000,3732.24 ccw(c3612.94,3732.24)

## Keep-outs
Board Outline Layer:
  circle w10: c3612.94,3737.24 r551.18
